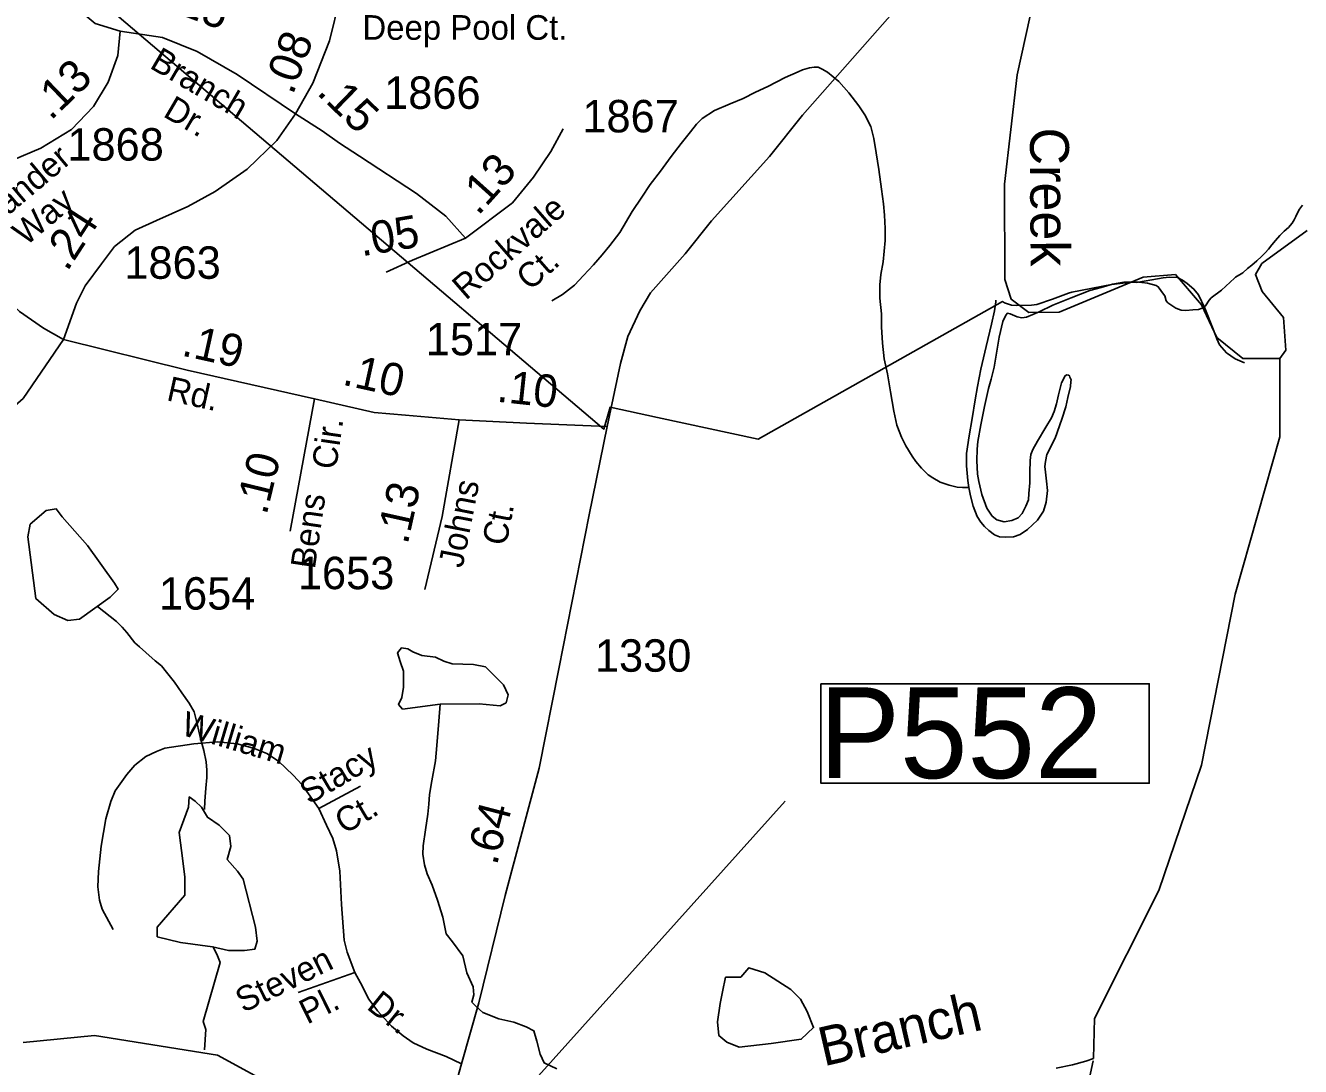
# Model space of a CAD drawing. Extents: x 2082433 to 2279600, y 546599 to 755198.
# Drawn here: x 2134776 to 2139693, y 647033 to 651046 of the extents above; entities that cross this region are included whole.
import ezdxf

# ---------------------------------------------------------------- set-up
doc = ezdxf.new("R2010")
doc.units = 0
for name, color, linetype in [('Exist Boundary Political Fire Districts', 7, 'Continuous'), ('Exist Hydrographic Creek Single Shore', 7, 'Continuous'), ('Exist Hydrographic Creek Single Shore Label', 7, 'Continuous'), ('Exist Hydrographic Misc Water Feature', 7, 'Continuous'), ('Exist Hydrographic Pond Over 1500 Sq Ft', 7, 'Continuous'), ('Exist Road Non-System Type 51', 7, 'Continuous'), ('Exist Road Non-System Type 51 Label', 7, 'Continuous'), ('Exist Road Secondary Mileage Hundredths English Label', 7, 'Continuous'), ('Exist Road Secondary Structure Pipe Number Label', 7, 'Continuous'), ('Exist Road Secondary Type 51 Attributed', 7, 'Continuous'), ('Exist Road Secondary Type 51 Label', 7, 'Continuous'), ('Exist Road Secondary Type 51 Number Label', 7, 'Continuous')]:
    doc.layers.add(name, color=color, linetype=linetype)

msp = doc.modelspace()

# ---------------------------------------------------------------- linework, layer by layer
at = {"layer": 'Exist Boundary Political Fire Districts'}
msp.add_lwpolyline([(2126117, 658742.4), (2137007.1, 649490.6), (2137030.7, 649574.7), (2137213.8, 649535.1), (2137602.4, 649452.1), (2138544.2, 649981.9), (2138551.5, 649977.3), (2138578.4, 649967.9), (2138598.5, 649966.8), (2138655.7, 649968.3), (2138676, 649970.7), (2138736.5, 649990.8), (2138798.4, 650014.8), (2138810.9, 650018.1), (2138964.7, 650047.9), (2139041, 650057.2), (2139060.1, 650058.1), (2139103.7, 650053.2), (2139137.2, 650043.8), (2139144.8, 650039.2), (2139165.3, 650011.1), (2139169.6, 650003.6), (2139175.7, 649984.4), (2139182.1, 649977.7), (2139212.2, 649956.5), (2139232.9, 649949.5), (2139251.6, 649947.6), (2139278.2, 649949.7), (2139300.6, 649951.5), (2139314.5, 649956.2), (2139327, 649966), (2139341, 649988), (2139349.2, 649996.9), (2139389, 650026.3), (2139438.6, 650072.7), (2139443.3, 650076.4), (2139471, 650092.9), (2139488.8, 650109.8), (2139505.9, 650122.8), (2139525.5, 650139), (2139543.2, 650155.6), (2139557.7, 650170.3), (2139570.2, 650184.5), (2139583, 650200.3), (2139596.7, 650217.5), (2139613.7, 650236.9), (2139630.9, 650253.7), (2139646.5, 650267.6), (2139660.7, 650284.9), (2139668.7, 650297.6), (2139675.2, 650309.9), (2139681, 650321.7), (2139690, 650338.3), (2139701.5, 650354.1)], dxfattribs=at)
at = {"layer": 'Exist Hydrographic Creek Single Shore'}
for points in [[(2139613.1, 649763), (2139471, 649762.6), (2139371.2, 649843.4), (2139312.1, 649969.2), (2139211, 650086.1), (2139086.1, 650075.5), (2138762.2, 649941), (2138645.1, 649940.1), (2138578, 649990.7), (2138553.2, 650066.7), (2138552.2, 650434.1), (2138600.2, 650856.3), (2138698.2, 651300.4)], [(2139719.1, 650256.2), (2139544, 650128.5), (2139519.2, 650086.4), (2139545.1, 650020.3), (2139628.1, 649920.2), (2139637.1, 649795.3), (2139613.1, 649763)], [(2138895.4, 647063.8), (2138899.1, 647218.8), (2139147, 647712.4), (2139311.1, 648194.6), (2139441.1, 648854.6), (2139614.1, 649461.2), (2139613.1, 649763)], [(2135053.4, 648807.2), (2135127.2, 648748.3), (2135149.5, 648726.7), (2135167.6, 648707), (2135197.7, 648666.7), (2135215.5, 648651), (2135239.9, 648629.1), (2135275.8, 648597.3), (2135300.2, 648577.4), (2135320.3, 648553.2), (2135350.3, 648515.5), (2135378.6, 648473.9), (2135406.9, 648433.9), (2135426.5, 648400.1), (2135438.8, 648354), (2135451.4, 648298.2), (2135463.7, 648252.1), (2135473.3, 648208.1), (2135475.6, 648176.1), (2135475.6, 648148.1), (2135472.1, 648106.5), (2135468, 648056.4), (2135466.9, 648023.5)], [(2136376.1, 648430.1), (2136370.6, 648364.3), (2136363, 648270.2), (2136357.3, 648212.3), (2136343.7, 648134), (2136333.9, 648082), (2136332.3, 648044.1), (2136328, 648006.2), (2136318.3, 647946), (2136310.5, 647883.9), (2136309.1, 647852.1), (2136314.8, 647810.2), (2136325.3, 647776.2), (2136345.2, 647732.3), (2136365.7, 647674.4), (2136385.8, 647608.5), (2136398.1, 647544.6), (2136423.4, 647513.8), (2136462.8, 647460.4), (2136478.2, 647394.4), (2136502.1, 647341), (2136504.9, 647310.1), (2136497.9, 647282), (2136513.3, 647266.6), (2136539.4, 647241.4), (2136601.8, 647217.4), (2136659.4, 647204.8), (2136707.2, 647186.5), (2136736.7, 647171.1), (2136747.9, 647131.7), (2136760.6, 647081.2), (2136776, 647047.4), (2136825, 647024.2)], [(2135498.7, 647496.5), (2135514.7, 647466.5), (2135527.2, 647434.6), (2135461.6, 647207.5), (2135471.6, 647175.6), (2135466.8, 647098)], [(2135901.6, 646867.7), (2135516.9, 647077.6), (2135042, 647152.9), (2134767.1, 647125.7)], [(2138044.6, 644632.1), (2138427, 644627.1), (2138601.9, 644692.4), (2138710, 644801.8), (2138833.8, 645002.6), (2138907.9, 645060.2), (2139099, 645361.4), (2139248.1, 645538.8), (2139296.9, 645672.2), (2139313.1, 645888.4), (2139211, 646320.2), (2139159.9, 646445.9), (2138900.9, 646802.2), (2138859.1, 646894.9), (2138893.6, 647055.5)], [(2138751.7, 647027.1), (2138813.6, 647039.3), (2138865.3, 647053.7), (2138895.4, 647063.8)]]:
    msp.add_lwpolyline(points, dxfattribs=at)
at = {"layer": 'Exist Hydrographic Misc Water Feature'}
for points in [[(2136805.7, 649985.3), (2136847.6, 650009.8), (2136893.1, 650045.9), (2136928.8, 650081.9), (2136966.5, 650124), (2137000.5, 650162.3), (2137030.3, 650198.4), (2137068.4, 650248.6), (2137115.8, 650328.6), (2137153.5, 650384.9), (2137185.3, 650432.8), (2137225.1, 650485.2), (2137266.9, 650541.4), (2137304.4, 650591.7), (2137340.3, 650635.7), (2137364.5, 650665.7), (2137386, 650687.6), (2137434, 650718.1), (2137494.1, 650744.3), (2137543.7, 650764.3), (2137591.5, 650788.7), (2137639.3, 650810.7), (2137705.5, 650845.3), (2137755.5, 650867.4), (2137773.4, 650875.6), (2137799.4, 650883.4), (2137817.2, 650885.6), (2137832.8, 650885.7), (2137849, 650877.9), (2137869.1, 650866), (2137913.4, 650830.1), (2137951.6, 650786.2), (2137989.5, 650736.6), (2138013.7, 650702.5), (2138036.2, 650656.6), (2138048.5, 650610.9), (2138056.5, 650554.9), (2138066.8, 650490.9), (2138077, 650414.8), (2138085.2, 650359.2), (2138089.4, 650315.1), (2138091.8, 650263.3), (2138092.2, 650217), (2138084, 650135.1), (2138074.8, 650087), (2138070.7, 650047), (2138070.9, 649995.1), (2138077, 649934.9), (2138077.7, 649885), (2138081.8, 649821.1), (2138088.1, 649761.3), (2138100, 649703.1), (2138112.7, 649633.5), (2138125, 649559.4), (2138136.7, 649505.3), (2138155.2, 649459.6), (2138171.6, 649425.8), (2138195.6, 649385.7), (2138209.5, 649365.8), (2138232.1, 649340), (2138257.5, 649314.3), (2138275.9, 649302.2), (2138303.8, 649286.2), (2138338.1, 649274.6), (2138369.9, 649266.5), (2138390, 649264.7), (2138404.1, 649265), (2138413.7, 649264.7)], [(2138413.7, 649264.7), (2138420.3, 649232.9), (2138430.4, 649192.8), (2138446.6, 649153.1), (2138460.3, 649131.1), (2138474.6, 649115.1), (2138490.8, 649099.3), (2138512.8, 649083.5), (2138532.7, 649075.6), (2138554.8, 649073.4), (2138586.6, 649075.5), (2138612.6, 649083.8), (2138640.7, 649103.9), (2138678.7, 649139.9), (2138702, 649174), (2138712.5, 649208.2), (2138718, 649254), (2138713.7, 649289.9), (2138709.6, 649324.2), (2138707.4, 649346), (2138709.4, 649366), (2138715, 649391.9), (2138747, 649456), (2138772.6, 649528.4), (2138788.8, 649576.2), (2138796.4, 649612.4), (2138806.4, 649654.3), (2138808.1, 649674.3), (2138808.3, 649680.4), (2138804, 649690.4), (2138801.9, 649696.4), (2138798, 649698.1), (2138791.9, 649700.2), (2138786.1, 649696.3), (2138772.2, 649668.4), (2138760.3, 649622.3), (2138752.5, 649588.2), (2138742.9, 649558), (2138732.8, 649534), (2138711.1, 649498), (2138679.1, 649444), (2138661.4, 649411.8), (2138653.4, 649391.9), (2138651.4, 649369.9), (2138649.8, 649323.9), (2138650, 649283.7), (2138645.9, 649241.8), (2138644.4, 649217.7), (2138634, 649193.7), (2138620.4, 649165.7), (2138604.2, 649147.9), (2138580.5, 649137.7), (2138550.5, 649133.3), (2138522.4, 649141.2), (2138504.8, 649155.2), (2138484.3, 649185.1), (2138464.4, 649238.8), (2138452.3, 649288.9), (2138448, 649317.1), (2138445.5, 649369), (2138447, 649413), (2138449.4, 649442.7), (2138460.9, 649507), (2138474.8, 649577.1), (2138490.2, 649646.9), (2138500.5, 649683.1), (2138512, 649729.2), (2138524.1, 649799.2), (2138531.2, 649845.2), (2138545.2, 649905.1), (2138557.3, 649929.2), (2138563.2, 649937.2), (2138573.1, 649935.3), (2138601, 649923.4), (2138619, 649919.5), (2138637, 649921.6), (2138685.2, 649941.9), (2138738.8, 649967.9), (2138808.9, 649996.2), (2138880.4, 650024.7), (2138924.5, 650036.7), (2138968.6, 650049.1), (2139012.5, 650057.1), (2139044.3, 650057.1), (2139060.3, 650055.5), (2139120.1, 650065.5), (2139164, 650073.9), (2139186.4, 650075.8), (2139218.6, 650074.2), (2139238.1, 650064.3), (2139256.5, 650052.2), (2139282.5, 650030.4), (2139300.6, 650008.6), (2139324.8, 649956.7), (2139359, 649868.8), (2139371.3, 649838.9), (2139381, 649814.8), (2139407.4, 649784.8), (2139441.3, 649761), (2139477.3, 649745.4)], [(2138518.7, 649987), (2138518.7, 649980.9), (2138513, 649946.9), (2138501.3, 649895.1), (2138481.4, 649808.9), (2138460.1, 649720.9), (2138448.2, 649654.9), (2138438.8, 649602.8), (2138427.1, 649530.8), (2138415.2, 649464.8), (2138405.5, 649396.5), (2138405.7, 649348.7), (2138410.1, 649292.9), (2138413.7, 649264.7)]]:
    msp.add_lwpolyline(points, dxfattribs=at)
at = {"layer": 'Exist Hydrographic Pond Over 1500 Sq Ft'}
for points in [[(2134855.8, 649176.9), (2134794, 649123.6), (2134785.6, 649075.8), (2134816.5, 648837), (2134886.7, 648775.2), (2134940.1, 648752.7), (2134985, 648758.3), (2135103, 648842.6), (2135133.9, 648873.5), (2135119.9, 648896), (2135015.9, 649042.1), (2134917.6, 649151.7), (2134895.1, 649182.6)], [(2136229.6, 648411.4), (2136376.1, 648430.1), (2136526, 648431.1), (2136607.4, 648424), (2136629.9, 648435.3), (2136638.3, 648466.2), (2136620.1, 648504.1), (2136549.9, 648574.3), (2136503.5, 648582.8), (2136422, 648585.6), (2136389, 648595.4), (2136358.1, 648610.9), (2136305.4, 648617.9), (2136270.3, 648631.9), (2136250.7, 648643.2), (2136226.8, 648647.4), (2136211.3, 648627.7), (2136221.2, 648594), (2136234.5, 648557.5), (2136234.5, 648495.7), (2136227.5, 648456.3), (2136214.8, 648428.3)], [(2135405, 648033.5), (2135368.5, 647935.2), (2135382.6, 647825.6), (2135391, 647763.8), (2135391, 647693.6), (2135284.2, 647570), (2135284.2, 647533.5), (2135374.1, 647511), (2135497.7, 647494.1), (2135559.6, 647480.1), (2135621.4, 647480.1), (2135660.7, 647485.7), (2135669.1, 647516.6), (2135663.5, 647570), (2135615.7, 647755.4), (2135593.3, 647786.3), (2135553.9, 647831.3), (2135568, 647881.8), (2135562.4, 647924), (2135523, 647963.3), (2135478.1, 647994.2), (2135455.6, 648033.5), (2135430.3, 648056), (2135407.8, 648072.9)], [(2137475.5, 647377.5), (2137534.5, 647377.5), (2137565.4, 647414.1), (2137627.2, 647394.4), (2137728.4, 647329.8), (2137764.9, 647293.3), (2137790.2, 647245.5), (2137815.5, 647183.7), (2137767.7, 647138.8), (2137652.5, 647121.9), (2137528.9, 647107.9), (2137481.2, 647127.5), (2137450.3, 647152.8), (2137444.6, 647206.2), (2137455.9, 647276.4), (2137464.3, 647321.4)]]:
    msp.add_lwpolyline(points, close=True, dxfattribs=at)
at = {"layer": 'Exist Road Non-System Type 51'}
for p, q in [((2135907.1, 648027.8), (2136068.5, 648114.2)), ((2136046.3, 647395.7), (2135828, 647318.3))]:
    msp.add_line(p, q, dxfattribs=at)
for points in [[(2135907.1, 648027.8), (2135843.9, 648119.4), (2135808.8, 648156.9), (2135751.5, 648210.9), (2135707.6, 648240.5), (2135655.9, 648261.1), (2135593, 648277.4), (2135517, 648284.6), (2135426, 648277.7), (2135313.4, 648261), (2135281.9, 648247.7), (2135240.8, 648227.8), (2135198.4, 648194.6), (2135166.9, 648158.4), (2135122.6, 648096.2), (2135104.9, 648055.5), (2135086.7, 647987.7), (2135068.1, 647882.4), (2135058.3, 647784.9), (2135055.2, 647726), (2135061.8, 647674.7), (2135072.3, 647639.4), (2135114, 647562.1)], [(2136046.3, 647395.7), (2136017.2, 647473.9), (2136005.7, 647520.8), (2135994.5, 647658.5), (2135988.7, 647785.9), (2135975.4, 647864.4), (2135961.8, 647911.7), (2135937.6, 647964), (2135907.1, 648027.8)], [(2136457.8, 647043.2), (2136398.6, 647072.5), (2136324.1, 647100.3), (2136271.1, 647125.3), (2136233, 647151.8), (2136187.3, 647189.1), (2136133.9, 647247.6), (2136100.2, 647293.2), (2136068.5, 647356.2), (2136046.3, 647395.7)]]:
    msp.add_lwpolyline(points, dxfattribs=at)
at = {"layer": 'Exist Road Secondary Structure Pipe Number Label'}
msp.add_line((2136476.7, 646689.8), (2137706.6, 648056.3), dxfattribs=at)
msp.add_lwpolyline([(2137843.7, 648509.1), (2139109.9, 648509.1), (2139109.9, 648125.2), (2137843.7, 648125.2)], close=True, dxfattribs=at)
at = {"layer": 'Exist Road Secondary Type 51 Attributed'}
for points in [[(2138850.6, 652061.1), (2138723.4, 651878.9), (2138512.9, 651578.7), (2138235.7, 651226.7), (2137773.3, 650700.6), (2137645, 650541.5), (2137421.6, 650292.7), (2137320, 650166.6), (2137186.2, 650015.5), (2137145.4, 649946.7), (2137099.1, 649847), (2137071, 649743), (2137019, 649500)], [(2134923.2, 649835.7), (2134846, 649879.3), (2134753.3, 649943.9), (2134535.3, 650146.3), (2134379.3, 650273.1), (2134195.6, 650428.4), (2134062.9, 650517.3), (2133504.5, 650872.4), (2133147.2, 651070), (2132848.3, 651209.2), (2132518.8, 651343.3), (2132356.1, 651409.5), (2132157.2, 651472.4), (2131719.5, 651573.4)], [(2134877.4, 651563.9), (2134883.1, 651458.3), (2134907.7, 651280.6), (2134942.6, 651149.5), (2134985, 651104), (2135045.6, 651054), (2135141.1, 651024.5)], [(2135817, 650705.4), (2135884.1, 650824.3), (2135948.2, 650987.6), (2135989, 651150.9)], [(2135141.1, 651024.5), (2135132, 650930.5), (2135095.6, 650827.5), (2135038, 650733.5), (2134953.2, 650645.6), (2134835, 650572.9), (2134725.9, 650527.4)], [(2135141.1, 651024.5), (2135304.7, 651000.2), (2135438.1, 650945.7), (2135592.7, 650857.8), (2135817, 650705.4)], [(2134923.2, 649835.7), (2134972.4, 649976.2), (2135006.1, 650042.2), (2135069, 650128), (2135120, 650193.7), (2135198.8, 650257.8), (2135281.9, 650294.3), (2135402.9, 650348.9), (2135507.9, 650405.8), (2135631.8, 650492.6), (2135745.5, 650603.4), (2135817, 650705.4)], [(2135817, 650705.4), (2135920.5, 650639.8), (2135987.6, 650593.2), (2136064.9, 650542.1), (2136283.6, 650398.5), (2136397.3, 650311), (2136473.1, 650226.5)], [(2136473.1, 650226.5), (2136653.9, 650362.1), (2136735.6, 650461.2), (2136802.6, 650560.4), (2136849.3, 650647.8)], [(2136166.9, 650095.2), (2136269, 650141.9), (2136473.1, 650226.5)], [(2132892.8, 648234.4), (2133193.4, 648495.7), (2133657.4, 648894.1), (2133867.4, 649080.4), (2134060, 649231.7), (2134204.8, 649316.1), (2134404.5, 649383), (2134585.9, 649470.5), (2134694.1, 649543.8), (2134767.3, 649608.2), (2134923.2, 649835.7)], [(2135890.4, 649606.8), (2135399.8, 649717.4), (2134923.2, 649835.7)], [(2135890.4, 649606.8), (2135797.6, 649096.9)], [(2136448.5, 649526.3), (2136242.4, 649543.8), (2136121.5, 649554.9), (2135890.4, 649606.8)], [(2137019, 649500), (2136949.5, 649160.1), (2136833.6, 648565.9), (2136757, 648183.8), (2136625.7, 647692.2), (2136524.6, 647279.2), (2136457.8, 647043.2), (2136274.5, 646384.4), (2136132.7, 645883)], [(2136448.5, 649526.3), (2136382.7, 649153.1), (2136316.4, 648871.8)], [(2137019, 649500), (2136707.8, 649513.5), (2136448.5, 649526.3)]]:
    msp.add_lwpolyline(points, dxfattribs=at)

# ---------------------------------------------------------------- texts
at = {"layer": 'Exist Hydrographic Creek Single Shore Label'}
for s, rotation, p in [('Creek', 270.263, (2138650, 650652.6)), ('Branch', 12.9898, (2137854.3, 647033.5))]:
    msp.add_text(s, height=150, rotation=rotation, dxfattribs=at).set_placement(p)
at = {"layer": 'Exist Road Non-System Type 51 Label'}
for s, rotation, p in [('William', 343.4319, (2135371.6, 648313.4)), ('Stacy', 30.4618, (2135869.7, 648041)), ('Ct.', 30.4618, (2136005.5, 647926.6)), ('Steven', 26.3651, (2135616.3, 647238.7)), ('Pl.', 26.3651, (2135862.6, 647194.5)), ('Dr.', 321.2853, (2136088, 647258.4))]:
    msp.add_text(s, height=95, rotation=rotation, dxfattribs=at).set_placement(p)
at = {"layer": 'Exist Road Secondary Mileage Hundredths English Label'}
for s, rotation, p in [('.15', 339.5717, (2135315.9, 651108.5)), ('.08', 69.6036, (2135807.1, 650775.7)), ('.13', 43.9067, (2134873.7, 650676.9)), ('.15', 315.8601, (2135896.2, 650784.2)), ('.13', 48.092, (2136521.8, 650310)), ('.24', 57.0678, (2134936.9, 650094.6)), ('.05', 9.4797, (2136072.8, 650156.3)), ('.19', 347.5823, (2135374.3, 649774.7)), ('.10', 347.5823, (2135994.4, 649662.4)), ('.10', 353.927, (2136591, 649596.3)), ('.10', 76.307, (2135705.7, 649156.1)), ('.13', 77.4777, (2136249.8, 649042.6)), ('.64', 75.3625, (2136593.7, 647805.5))]:
    msp.add_text(s, height=125, rotation=rotation, dxfattribs=at).set_placement(p)
at = {"layer": 'Exist Road Secondary Structure Pipe Number Label'}
msp.add_text('P552', height=350, dxfattribs=at).set_placement((2137836.6, 648145))
at = {"layer": 'Exist Road Secondary Type 51 Label'}
msp.add_text('Deep Pool Ct.', height=95, dxfattribs=at).set_placement((2136075.6, 650991.1))
for s, rotation, p in [('Branch', 329.6838, (2135251, 650884.6)), (' Dr.', 329.6838, (2135272.4, 650715.7)), ('Meander', 40.007, (2134574.3, 650199)), (' Way', 40.007, (2134750.4, 650170.6)), ('Rockvale', 41.1235, (2136474.3, 649984.5)), (' Ct.', 41.1235, (2136694.5, 649997.5)), ('Rd.', 347.51, (2135316.6, 649602.2)), ('Cir.', 81.7353, (2135974, 649331.6)), ('Johns', 78.9027, (2136461.9, 648952.1)), ('Bens', 81.7353, (2135892.1, 648948.3)), ('Ct.', 78.9027, (2136629.9, 649037.4))]:
    msp.add_text(s, height=95, rotation=rotation, dxfattribs=at).set_placement(p)
at = {"layer": 'Exist Road Secondary Type 51 Number Label'}
for s, p in [('1866', (2136159.5, 650724.9)), ('1867', (2136923.9, 650634.2)), ('1868', (2134937.9, 650525.4)), ('1863', (2135157.6, 650069.8)), ('1517', (2136320.2, 649774.9)), ('1653', (2135826.7, 648873.4)), ('1654', (2135291, 648794.6)), ('1330', (2136972.2, 648555.2))]:
    msp.add_text(s, height=125, dxfattribs=at).set_placement(p)

doc.saveas('drawing.dxf')
